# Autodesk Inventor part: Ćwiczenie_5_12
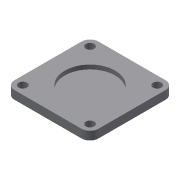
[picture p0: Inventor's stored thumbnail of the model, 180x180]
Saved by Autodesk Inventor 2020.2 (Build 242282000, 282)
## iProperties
Created: 2005-02
Part Number: Ćwiczenie_5_12
Document SubType Name: Modeling
Designer: F.Stasiak
Manufacturer: Standard
Standards Organization: Custom
Density: 1 g/cm^3
Material: Ogólny
Appearance: Domyślna
Manager: www.cadconsulting.pl
Company: Fabian Stasiak CAD Consulting
Author: F.Stasiak
Subject: Zbiór ćwiczeń. Autodesk Inventor 2020. Kurs podstawowy
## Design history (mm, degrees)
sketch "Szkic1"
  geometry: L1 (-50, 50)-(50, 50); L2 (50, 50)-(50, -50); L3 (50, -50)-(-50, -50); L4 (-50, -50)-(-50, 50); L5 (0, 50)-(0, -50); L6 (-50, 0)-(50, 0); 2 further points
  constraints: 12 end point, 5 midpoint, 2 parallel, 1 coincident, 1 horizontal, 1 perpendicular
  dimensions: "d0" = 100 distance of L2.end L3.end; "d1" = 100 distance of L3.end L1.start (= d0)
extrude "Wyciągnięcie proste1" new body sketch "Szkic1" distance "d2" = 10; taper "d3" = 0 deg
fillet "Zaokrąglenie1" dims "d4" = 10
sketch "Szkic2"
  geometry: A1 r 10 centre (40, -40) between (40, -50) and (50, -40) reference; A2 r 10 centre (40, 40) between (50, 40) and (40, 50) reference; A3 r 10 centre (-40, 40) between (-40, 50) and (-50, 40) reference; A4 r 10 centre (-40, -40) between (-50, -40) and (-40, -50) reference
hole "Otwór1" sketch "Szkic2" at (-40, 40), (40, 40), (40, -40), (-40, -40) diameter "d5" = 10; stored, may be unused: countersink angle "d9" = 90 deg, drill point angle "d11" = 118 deg; dims "d6" = 6, "d7" = 4, "d8" = 2, "d10" = 8
sketch "Szkic3"
  geometry: C1 r 30 at (0, 0); 1 further point
  constraints: 1 centre point, 1 coincident
  dimensions: "d12" = 60 diameter of C1 (computed from d0)
extrude "Wyciągnięcie proste2" cut sketch "Szkic3" distance "d13" = 5; taper "d14" = 0 deg
node "Bryła1"
node "Korpusy bryłowe"
node "Korpusy powierzchniowe"
